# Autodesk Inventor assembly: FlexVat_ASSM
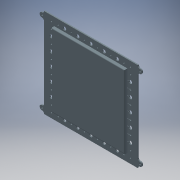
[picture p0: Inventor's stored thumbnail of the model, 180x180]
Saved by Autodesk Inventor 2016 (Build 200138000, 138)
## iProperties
Created: 2015-11
Part Number: FlexVat_ASSM
Document SubType Name: Assembly
Designer: John
Author: John
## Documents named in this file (6)
- D:\3D Printer Designs\John Ledden Designs\DLP Printer\V0-4\FlexVat_ASSM.iam
- D:\3D Printer Designs\John Ledden Designs\DLP Printer\V0-4\FlexVat_Base.ipt
- D:\3D Printer Designs\John Ledden Designs\DLP Printer\V0-4\Clear_VatBottom.ipt
- D:\3D Printer Designs\John Ledden Designs\DLP Printer\V0-4\FlexVat3\WallBase.ipt
- D:\3D Printer Designs\John Ledden Designs\DLP Printer\V0-4\FlexVat3\VatWall3.ipt
- D:\3D Printer Designs\John Ledden Designs\DLP Printer\V0-4\FlexVat3\Clamp_2-5D.ipt
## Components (5 placed, 5 different names)
1. FlexVat_Base_1070
2. Clear_VatBottom_1071 — Flush:1
3. WallBase:1 — Flush:2, Flush:3, Flush:4, Flush:5, Flush:6, Flush:7
4. VatWall3:1 — Flush:4, Flush:5
5. Clamp_2-5D:1 — Flush:6, Flush:7
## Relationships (7: Flush 7)
- Flush:1: Clear_VatBottom_1071
- Flush:2: WallBase:1
- Flush:3: WallBase:1
- Flush:4: WallBase:1 ↔ VatWall3:1
- Flush:5: WallBase:1 ↔ VatWall3:1
- Flush:6: WallBase:1 ↔ Clamp_2-5D:1
- Flush:7: WallBase:1 ↔ Clamp_2-5D:1
